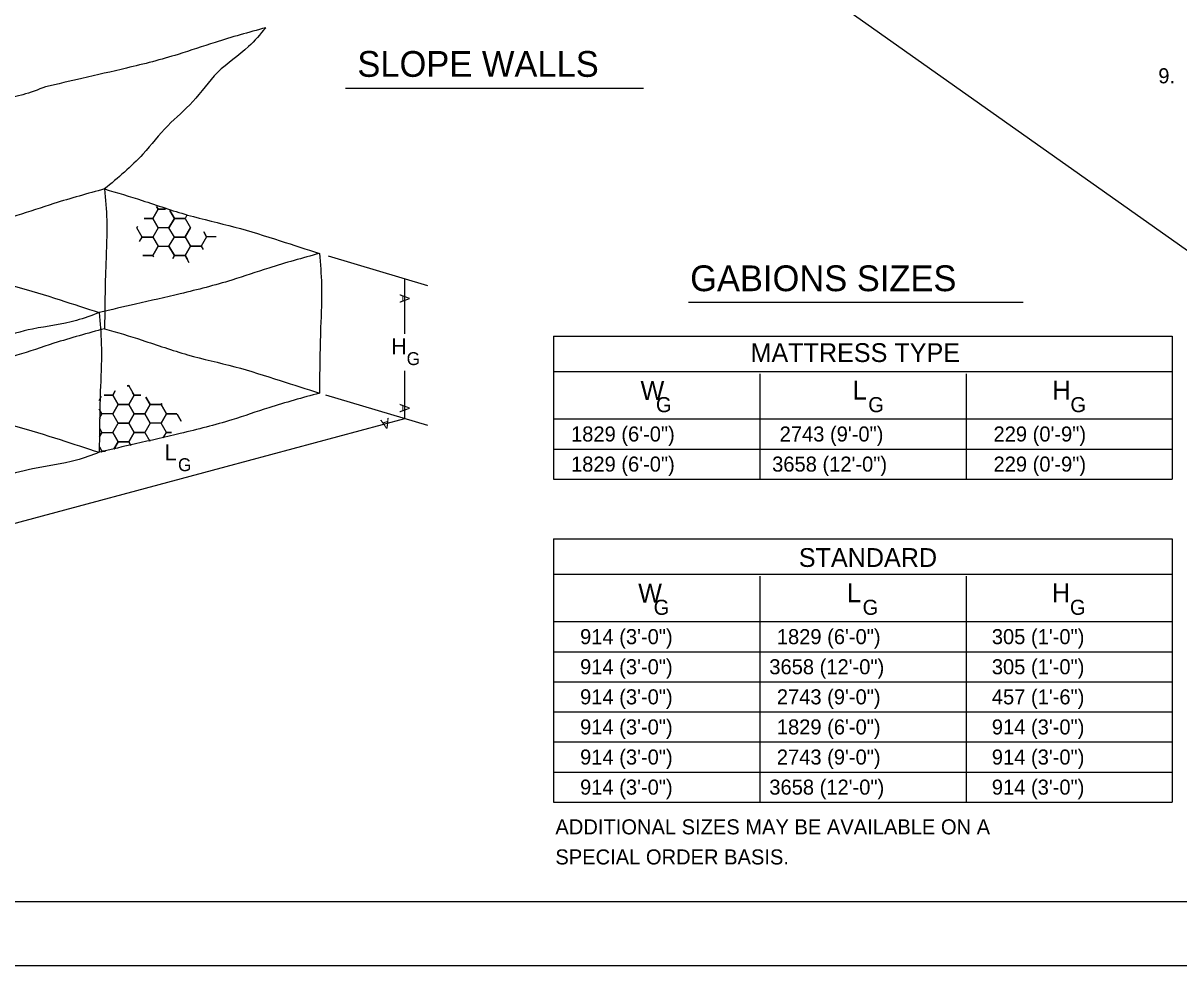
# Model space of a CAD drawing. Extents: x 3 to 3592, y -602 to 1171.
# Drawn here: x 3022.2 to 3291.2, y -601.8 to -382.5 of the extents above; entities that cross this region are included whole.
import ezdxf

# ---------------------------------------------------------------- set-up
doc = ezdxf.new("R2010")
doc.units = 0
for name, color, linetype in [('1', 7, 'Continuous'), ('2', 7, 'Continuous'), ('3', 7, 'Continuous')]:
    doc.layers.add(name, color=color, linetype=linetype)

msp = doc.modelspace()

# ---------------------------------------------------------------- linework, layer by layer
at = {"layer": '1'}
msp.add_line((2687.88, -7.81), (3528.88, -601.81), dxfattribs=at)
msp.add_lwpolyline([(2687.88, -7.81), (3528.88, -7.81), (3528.88, -601.81), (2687.88, -601.81)], close=True, dxfattribs=at)
msp.add_lwpolyline([(3512.88, -586.81), (3512.88, -22.81), (2726.88, -22.81), (2726.88, -586.81), (3512.88, -586.81), (3512.88, -560.45), (3312.88, -560.45), (3312.88, -495.77), (3512.88, -495.77), (3512.88, -466.81), (3312.88, -466.81), (3312.88, -586.81), (3391.68, -586.81), (3391.68, -560.45), (3391.68, -586.81), (3468.68, -586.81), (3468.68, -560.45), (3468.68, -572.77), (3512.88, -572.77)], dxfattribs=at)
at = {"layer": '2'}
for p, q in [((3116.37, -443.65), (3093.27, -436.72)), ((3110.97, -442.03), (3110.97, -454.78)), ((3041.21, -449.37), (3041.16, -453.59)), ((3110.97, -463.42), (3110.97, -474.53)), ((3116.37, -476.15), (3092.67, -469.05)), ((3110.97, -474.53), (3069.4, -485.69)), ((3069.4, -485.69), (3008.47, -502.03)), ((3242.96, -563.73), (3242.96, -563.73))]:
    msp.add_line(p, q, dxfattribs=at)
for points in [[(3053.65, -425.77), (3052.4, -427.94)], [(3052.4, -427.94), (3053.65, -425.77)], [(3053.28, -425.15), (3053.65, -425.77)], [(3053.65, -425.77), (3053.28, -425.15)], [(3053.65, -425.77), (3055.3, -425.77)], [(3055.3, -425.77), (3053.65, -425.77)], [(3056.33, -426.09), (3057.4, -427.94)], [(3057.4, -427.94), (3056.33, -426.09)], [(3060.26, -427.31), (3059.9, -427.94)], [(3048.65, -430.1), (3048.59, -430.1)], [(3048.81, -429.81), (3048.65, -430.1)], [(3048.65, -430.1), (3048.81, -429.81)], [(3049.9, -432.27), (3048.65, -430.1)], [(3052.4, -427.94), (3050.35, -427.94)], [(3050.35, -427.94), (3052.4, -427.94)], [(3053.65, -430.1), (3052.4, -427.94)], [(3052.4, -427.94), (3053.65, -430.1)], [(3053.65, -430.1), (3052.4, -432.27)], [(3056.15, -430.1), (3053.65, -430.1)], [(3057.4, -427.94), (3056.15, -430.1)], [(3059.9, -427.94), (3057.4, -427.94)], [(3059.91, -432.26), (3061.15, -430.13)], [(3049.3, -433.29), (3049.9, -432.27)], [(3049.9, -432.27), (3052.4, -432.27)], [(3052.4, -432.27), (3049.9, -432.27)], [(3052.4, -432.27), (3053.65, -434.43)], [(3061.16, -434.43), (3059.91, -432.26)], [(3064.91, -432.26), (3063.66, -434.43)], [(3064.91, -432.26), (3064.24, -431.09)], [(3064.24, -431.09), (3064.91, -432.26)], [(3067.16, -432.26), (3064.91, -432.26)], [(3053.65, -434.43), (3052.4, -436.6)], [(3052.4, -436.6), (3053.65, -434.43)], [(3053.65, -434.43), (3056.15, -434.43)], [(3056.15, -434.43), (3057.4, -436.6)], [(3059.91, -436.59), (3061.16, -434.43)], [(3061.16, -434.43), (3063.66, -434.43)], [(3063.66, -434.43), (3061.16, -434.43)], [(3063.66, -434.43), (3064.1, -435.19)], [(3050.04, -436.6), (3052.4, -436.6)], [(3052.4, -436.6), (3050.04, -436.6)], [(3052.4, -436.6), (3052.54, -436.85)], [(3052.54, -436.85), (3052.4, -436.6)], [(3057.4, -436.6), (3057.03, -437.24)], [(3057.03, -437.24), (3057.4, -436.6)], [(3057.4, -436.6), (3059.9, -436.6)], [(3059.9, -436.6), (3060.43, -437.53)], [(3060.88, -438.26), (3059.91, -436.59)], [(3043.65, -468.04), (3043.04, -469.08)], [(3043.04, -469.08), (3043.65, -468.04)], [(3046.42, -466.92), (3046.79, -466.92)], [(3046.79, -466.92), (3046.42, -466.92)], [(3046.91, -466.72), (3046.79, -466.92)], [(3046.79, -466.92), (3048.04, -469.08)], [(3040.38, -469.36), (3039.87, -470.26)], [(3039.87, -470.26), (3040.38, -469.36)], [(3041.07, -469.08), (3043.04, -469.08)], [(3043.04, -469.08), (3041.07, -469.08)], [(3043.04, -469.08), (3044.29, -471.25)], [(3044.29, -471.25), (3043.04, -469.08)], [(3048.04, -469.08), (3046.79, -471.25)], [(3046.79, -471.25), (3048.04, -469.08)], [(3048.04, -469.08), (3047.68, -468.45)], [(3049.56, -469.08), (3048.04, -469.08)], [(3048.04, -469.08), (3049.56, -469.08)], [(3051.79, -471.25), (3050.77, -469.49)], [(3050.77, -469.49), (3051.79, -471.25)], [(3040.54, -473.41), (3039.89, -472.29)], [(3039.89, -472.29), (3040.54, -473.41)], [(3040.54, -473.41), (3039.92, -474.48)], [(3043.04, -473.41), (3040.54, -473.41)], [(3044.29, -471.25), (3043.04, -473.41)], [(3046.79, -471.25), (3044.29, -471.25)], [(3048.04, -473.41), (3046.79, -471.25)], [(3050.54, -473.41), (3048.04, -473.41)], [(3051.79, -471.25), (3050.54, -473.41)], [(3050.54, -473.41), (3051.79, -471.25)], [(3051.79, -475.58), (3050.54, -473.41)], [(3054.29, -471.25), (3051.79, -471.25)], [(3051.79, -471.25), (3054.29, -471.25)], [(3054.45, -470.97), (3054.29, -471.25)], [(3054.29, -471.25), (3054.45, -470.97)], [(3055.54, -473.41), (3054.29, -471.25)], [(3054.29, -471.25), (3055.54, -473.41)], [(3055.54, -473.41), (3054.29, -475.58)], [(3054.29, -475.58), (3055.54, -473.41)], [(3058, -473.41), (3055.54, -473.41)], [(3055.54, -473.41), (3058, -473.41)], [(3054.29, -475.58), (3051.79, -475.58)], [(3055.54, -477.74), (3054.29, -475.58)], [(3059.01, -475.08), (3058.07, -473.47)], [(3058.07, -473.47), (3059.01, -475.08)], [(3039.96, -476.72), (3040.54, -477.74)], [(3040.54, -477.74), (3039.98, -478.71)], [(3039.98, -478.71), (3040.54, -477.74)], [(3040.54, -477.74), (3043.04, -477.74)], [(3043.04, -477.74), (3044.29, -479.91)], [(3046.79, -479.91), (3048.04, -477.74)], [(3048.04, -477.74), (3050.54, -477.74)], [(3050.54, -477.74), (3051.69, -479.73)], [(3054.81, -479.02), (3055.54, -477.74)], [(3055.54, -477.74), (3056.74, -477.74)], [(3056.74, -477.74), (3055.54, -477.74)], [(3040.02, -481.16), (3040.54, -482.07)], [(3040.54, -482.07), (3040.02, -481.16)], [(3044.29, -479.91), (3043.29, -481.64)], [(3043.29, -481.64), (3044.29, -479.91)], [(3044.29, -479.91), (3046.79, -479.91)], [(3046.79, -479.91), (3047.27, -480.73)], [(3047.27, -480.74), (3046.79, -479.91)], [(3040.36, -482.38), (3040.34, -482.43)], [(3040.34, -482.43), (3040.36, -482.38)], [(3040.54, -482.07), (3040.41, -482.3)], [(3040.41, -482.3), (3040.54, -482.07)], [(3040.54, -482.07), (3041.41, -482.07)], [(3041.41, -482.07), (3040.54, -482.07)]]:
    msp.add_lwpolyline(points, dxfattribs=at)
for points in [[(3056.15, -430.1), (3057.4, -427.94), (3059.9, -427.94), (3061.15, -430.1), (3059.9, -432.27), (3057.4, -432.27)], [(3056.15, -434.43), (3057.4, -432.27), (3059.9, -432.27), (3061.15, -434.43), (3059.9, -436.6), (3057.4, -436.6)], [(3043.04, -473.41), (3044.29, -471.25), (3046.79, -471.25), (3048.04, -473.41), (3046.79, -475.58), (3044.29, -475.58)], [(3046.79, -475.58), (3048.04, -473.41), (3050.54, -473.41), (3051.79, -475.58), (3050.54, -477.74), (3048.04, -477.74)], [(3043.04, -477.74), (3044.29, -475.58), (3046.79, -475.58), (3048.04, -477.74), (3046.79, -479.91), (3044.29, -479.91)]]:
    msp.add_lwpolyline(points, close=True, dxfattribs=at)
for points in [[(3078.66, -383.59), (3066.87, -386.99), (3058.27, -389.79), (3046.28, -392.98), (3035.89, -395.38), (3027.41, -397.34)], [(3078.66, -383.59), (3074.66, -387.99), (3067.47, -393.98), (3061.67, -400.78), (3055.88, -406.37), (3050.08, -412.97), (3041.16, -421.09)], [(3027.41, -397.34), (3022.1, -399.18), (3011.91, -401.18), (2996.13, -405.77), (2986.53, -408.37), (2976.16, -411.09)], [(3041.16, -421.09), (3029.37, -424.49), (3020.77, -427.29), (3008.78, -430.48), (2998.39, -432.88), (2989.91, -434.84)], [(3041.16, -421.09), (3049.88, -423.76), (3060.47, -427.15), (3071.46, -429.95), (3082.05, -433.15), (3091.16, -436.09)], [(3041.16, -421.09), (3041.65, -428.34), (3041.45, -438.33), (3041.25, -446.33), (3041.21, -449.37)], [(2989.91, -434.84), (2998.63, -437.51), (3009.22, -440.9), (3020.21, -443.7), (3030.8, -446.9), (3039.91, -449.84)], [(3091.16, -436.09), (3079.37, -439.49), (3070.77, -442.29), (3058.78, -445.48), (3048.39, -447.88), (3039.91, -449.84)], [(3091.16, -436.09), (3091.65, -443.34), (3091.45, -453.33), (3091.25, -461.33), (3091.16, -468.59)], [(3039.91, -449.84), (3034.6, -451.68), (3024.41, -453.68), (3008.63, -458.27), (2999.03, -460.87), (2988.66, -463.59)], [(3039.91, -449.84), (3040.4, -457.09), (3040.2, -467.08), (3040, -475.08), (3039.91, -482.34)], [(3041.16, -453.59), (3029.37, -456.99), (3020.77, -459.79), (3008.78, -462.98), (2998.39, -465.38), (2989.91, -467.34)], [(3041.16, -453.59), (3049.88, -456.26), (3060.47, -459.65), (3071.46, -462.45), (3082.05, -465.65), (3091.16, -468.59)], [(2989.91, -467.34), (2998.63, -470.01), (3009.22, -473.4), (3020.21, -476.2), (3030.8, -479.4), (3039.91, -482.34)], [(3091.16, -468.59), (3079.37, -471.99), (3070.77, -474.79), (3058.78, -477.98), (3048.39, -480.38), (3039.91, -482.34)], [(3039.91, -482.34), (3034.6, -484.18), (3024.41, -486.18), (3008.63, -490.77), (2999.03, -493.37), (2988.66, -496.09)]]:
    msp.add_spline(points, degree=3, dxfattribs=at)
at = {"layer": '3'}
for p, q in [((3097.24, -397.63), (3166.59, -397.63)), ((3177.04, -447.44), (3254.95, -447.44)), ((3145.67, -455.3), (3289.67, -455.3)), ((3145.67, -455.3), (3145.67, -488.59)), ((3289.67, -455.3), (3289.67, -488.59)), ((3145.67, -463.56), (3289.67, -463.56)), ((3193.67, -464.06), (3193.67, -488.59)), ((3241.67, -464.06), (3241.67, -488.59)), ((3145.67, -474.59), (3289.67, -474.59)), ((3145.67, -481.59), (3289.67, -481.59)), ((3145.67, -488.59), (3289.67, -488.59)), ((3202.17, -488.59), (3228.03, -488.59)), ((3230.55, -488.59), (3253.99, -488.59)), ((3145.67, -502.44), (3289.67, -502.44)), ((3145.67, -502.44), (3145.67, -563.73)), ((3289.67, -502.44), (3289.67, -563.73)), ((3145.67, -510.69), (3289.67, -510.69)), ((3193.67, -511.19), (3193.67, -563.73)), ((3241.67, -511.19), (3241.67, -563.73)), ((3145.67, -521.73), (3289.67, -521.73)), ((3145.67, -528.73), (3289.67, -528.73)), ((3145.67, -535.73), (3289.67, -535.73)), ((3193.67, -535.73), (3219.52, -535.73)), ((3219.52, -535.73), (3242.96, -535.73)), ((3145.67, -542.73), (3289.67, -542.73)), ((3145.67, -549.73), (3289.67, -549.73)), ((3145.67, -556.73), (3289.67, -556.73)), ((3145.67, -563.73), (3289.67, -563.73))]:
    msp.add_line(p, q, dxfattribs=at)

# ---------------------------------------------------------------- texts
at = {"layer": '2'}
for rotation, p in [(270, (3109.8, -445.53)), (270, (3109.8, -471.03)), (195.0184, (3107.28, -474.31))]:
    msp.add_text('A', height=2.33, rotation=rotation, dxfattribs=at).set_placement(p)
at = {"layer": '3'}
for s, height, p in [('SLOPE WALLS', 6, (3099.99, -395.01)), ('9.  ', 3.5, (3286.41, -396.52)), ('GABIONS SIZES', 6, (3177.45, -444.87)), ('H', 3.75, (3107.87, -459.55)), ('MATTRESS TYPE', 4.375, (3191.5, -461.35)), ('G', 3, (3111.46, -462.06)), ('W', 4.38, (3165.9, -470.15)), ('L', 4.38, (3215.28, -470.08)), ('H', 4.38, (3261.76, -470.08)), ('G', 3.5, (3169.49, -473.01)), ('G', 3.5, (3218.9, -473.01)), ('G', 3.5, (3265.95, -473.01)), ('1829 (6\'-0")', 3.5, (3149.72, -479.84)), ('2743 (9\'-0")', 3.5, (3198.28, -479.84)), ('229 (0\'-9")', 3.5, (3248.05, -479.84)), ('L', 3.75, (3055.14, -484.22)), ('G', 3, (3058.24, -486.73)), ('1829 (6\'-0")', 3.5, (3149.72, -486.84)), ('3658 (12\'-0")', 3.5, (3196.53, -486.84)), ('229 (0\'-9")', 3.5, (3248.05, -486.84)), ('STANDARD', 4.375, (3202.74, -509.01)), ('W', 4.38, (3165.36, -517.29)), ('L', 4.38, (3213.97, -517.22)), ('H', 4.38, (3261.65, -517.22)), ('G', 3.5, (3168.95, -520.15)), ('G', 3.5, (3217.59, -520.15)), ('G', 3.5, (3265.84, -520.15)), ('914 (3\'-0")', 3.5, (3151.83, -526.98)), ('1829 (6\'-0")', 3.5, (3197.62, -526.98)), ('305 (1\'-0")', 3.5, (3247.66, -526.98)), ('914 (3\'-0")', 3.5, (3151.83, -533.98)), ('3658 (12\'-0")', 3.5, (3195.87, -533.98)), ('305 (1\'-0")', 3.5, (3247.66, -533.98)), ('914 (3\'-0")', 3.5, (3151.83, -540.98)), ('2743 (9\'-0")', 3.5, (3197.62, -540.98)), ('457 (1\'-6")', 3.5, (3247.66, -540.98)), ('914 (3\'-0")', 3.5, (3151.83, -547.98)), ('1829 (6\'-0")', 3.5, (3197.62, -547.98)), ('914 (3\'-0")', 3.5, (3247.66, -547.98)), ('914 (3\'-0")', 3.5, (3151.83, -554.98)), ('2743 (9\'-0")', 3.5, (3197.62, -554.98)), ('914 (3\'-0")', 3.5, (3247.66, -554.98)), ('914 (3\'-0")', 3.5, (3151.83, -561.98)), ('3658 (12\'-0")', 3.5, (3195.87, -561.98)), ('914 (3\'-0")', 3.5, (3247.66, -561.98)), ('ADDITIONAL SIZES MAY BE AVAILABLE ON A', 3.5, (3146.08, -571.22)), ('SPECIAL ORDER BASIS. ', 3.5, (3146.08, -578.22))]:
    msp.add_text(s, height=height, dxfattribs=at).set_placement(p)

doc.saveas('drawing.dxf')
